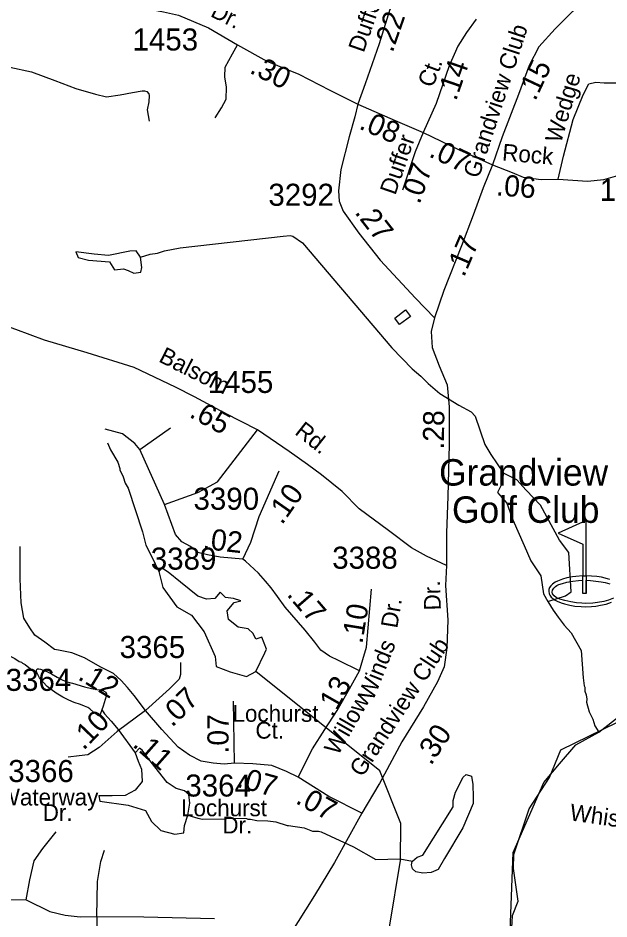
# Model space of a CAD drawing. Extents: x 1547597 to 1699558, y 810033 to 920809.
# Drawn here: x 1598301 to 1601652, y 878602 to 883710 of the extents above; entities that cross this region are included whole.
import ezdxf

# ---------------------------------------------------------------- set-up
doc = ezdxf.new("R2010")
doc.units = 0
for name, color, linetype in [('Exist Boundary Political City Limit New', 7, 'Continuous'), ('Exist Cultural Recreational Golf Course CELL', 7, 'Continuous'), ('Exist Cultural Recreational Golf Course Label', 7, 'Continuous'), ('Exist Hydrographic Creek Single Shore', 7, 'Continuous'), ('Exist Hydrographic Misc Water Feature', 7, 'Continuous'), ('Exist Road Non-System Type 51', 7, 'Continuous'), ('Exist Road Non-System Type 51 Label', 7, 'Continuous'), ('Exist Road Secondary Mileage Hundredths English Label', 7, 'Continuous'), ('Exist Road Secondary Type 51 Attributed', 7, 'Continuous'), ('Exist Road Secondary Type 51 Label', 7, 'Continuous'), ('Exist Road Secondary Type 51 Number Label', 7, 'Continuous'), ('Map Preparation Boundary City Limit Buffer Line', 7, 'Continuous')]:
    doc.layers.add(name, color=color, linetype=linetype)

msp = doc.modelspace()

# ---------------------------------------------------------------- linework, layer by layer
at = {"layer": 'Exist Boundary Political City Limit New'}
msp.add_lwpolyline([(1601102, 878552.4), (1601105.9, 878622.2), (1601138.3, 878702.8), (1601111, 878888.1), (1601113.6, 878968.7), (1601199.6, 879226.3), (1601315.8, 879403.5), (1601379.7, 879560.4), (1601858.9, 879795.7)], dxfattribs=at)
at = {"layer": 'Exist Cultural Recreational Golf Course CELL'}
for points in [[(1601657.7, 880526.5), (1601643.4, 880530.5), (1601610.4, 880539.3), (1601582.8, 880544.3), (1601523.3, 880548.2), (1601523.3, 880862.1), (1601364.8, 880788.7), (1601504.9, 880727.1), (1601504.9, 880548.2), (1601523.3, 880548.2), (1601523.3, 880523.2), (1601523.3, 880448.2), (1601523.3, 880523.2), (1601546.9, 880521.6), (1601577.5, 880518.4), (1601609, 880514.3), (1601630.2, 880510), (1601658, 880501.7)], [(1601677.2, 880420.8), (1601649.8, 880410.5), (1601623.3, 880403), (1601587.7, 880397.4), (1601560.7, 880393.4), (1601520.6, 880391.6), (1601498.1, 880393.4), (1601469.1, 880394.9), (1601436, 880399.4), (1601402, 880407), (1601372.9, 880415.5), (1601353.4, 880424), (1601341.4, 880433.5), (1601332.9, 880445.5), (1601330.4, 880455.5), (1601332.9, 880466.5), (1601339.9, 880477.5), (1601348.4, 880487.1), (1601357.5, 880492.4), (1601368.9, 880498.1), (1601388.1, 880504.6), (1601414.2, 880511.6), (1601447, 880517.6), (1601479.1, 880521.6), (1601504.9, 880523.2), (1601504.9, 880548.2), (1601523.3, 880548.2), (1601523.3, 880448.2), (1601504.9, 880448.2), (1601504.9, 880523.2), (1601504.9, 880548.2), (1601464.4, 880544.5), (1601444.9, 880542.8), (1601414.1, 880535.5), (1601388.6, 880529.2), (1601360.3, 880518.2), (1601347.9, 880511.1), (1601332.1, 880501.3), (1601321.9, 880490.3), (1601315.6, 880482.1), (1601311.6, 880469.8), (1601310.6, 880460), (1601313.4, 880445.5), (1601316.1, 880438.5), (1601325.1, 880426.2), (1601333.4, 880419.2), (1601347.3, 880409.6), (1601359, 880403.8), (1601381.6, 880394.3), (1601400.3, 880389.3), (1601430.6, 880382), (1601458.7, 880376.5), (1601495.1, 880373.2), (1601518.6, 880372.2), (1601552.4, 880374.2), (1601577.7, 880376.7), (1601604.1, 880381.3), (1601636.2, 880387.8), (1601667.2, 880398.3)]]:
    msp.add_lwpolyline(points, dxfattribs=at)
at = {"layer": 'Exist Hydrographic Creek Single Shore'}
for points in [[(1601039.7, 877845.7), (1600706.7, 877891.9), (1600549.6, 877993.5), (1600475.6, 878070.5), (1600386.6, 878230), (1600408, 878555), (1600469.4, 878933.7), (1600471.3, 879142.9), (1600352.4, 879442.3), (1599649.1, 880006)], [(1601076.6, 878137.2), (1601109.1, 878979.4), (1601282.9, 879376.8), (1601372, 879482), (1601463.8, 879588.8), (1601595.5, 879662.2), (1601723.6, 879762.2)]]:
    msp.add_lwpolyline(points, dxfattribs=at)
at = {"layer": 'Exist Hydrographic Misc Water Feature'}
msp.add_line((1600492.3, 878973), (1600492.3, 878973), dxfattribs=at)
for points in [[(1598995.8, 882353.6), (1599049.9, 882370.7), (1599091.5, 882377), (1599131.7, 882390.4), (1599219.9, 882406.9), (1599804.7, 882473.1), (1599844.8, 882476.4), (1599858.7, 882474.1), (1599914.1, 882435.2), (1600420.2, 881840.7), (1600536.3, 881720.8), (1600585.6, 881680), (1600626.9, 881637.3), (1600694, 881582.2), (1600800.8, 881514.4), (1600870.2, 881477.2), (1600893.8, 881452.8), (1600947.4, 881291.5), (1600982.4, 881234.9), (1601053.7, 881129.2)], [(1598995.8, 882353.6), (1598971.4, 882391.1), (1598934.8, 882388.5), (1598814.6, 882363.2), (1598733.6, 882371.1), (1598628.2, 882385), (1598641.3, 882351.9), (1598701.4, 882337.1), (1598819.9, 882327.5), (1598847.7, 882282.1), (1598900, 882289.1), (1598926.1, 882277.8), (1598957.5, 882263.8), (1598997.6, 882269.1), (1599002.8, 882296.1), (1598995.8, 882353.6)], [(1600497.8, 882055.6), (1600526.1, 882018.8), (1600465.2, 881972.4), (1600437.9, 882007.9), (1600497.8, 882055.6)], [(1598808.4, 881302), (1598825.7, 881261.7), (1598866.7, 881193), (1598878, 881156.8), (1598877.9, 881148.8), (1598897.3, 881108.5), (1598908.7, 881072.3), (1598926.2, 881044), (1599006.2, 880797), (1599025.2, 880720.8), (1599057.5, 880659.9), (1599099, 880571.4)], [(1601053.7, 881129.2), (1601039, 881057.7), (1601019.3, 881020.7), (1601073.4, 880959.1), (1601107.9, 880865.4), (1601172, 880720), (1601208.9, 880633.7), (1601265.5, 880547.5), (1601280.3, 880446.4), (1601304.9, 880402.5)], [(1601304.9, 880402.5), (1601405.9, 880434.1), (1601437.9, 880456.3), (1601425.6, 880680.6), (1601371.4, 880749.6), (1601263.1, 880949.2), (1601181.8, 881033), (1601130.1, 881092.2), (1601053.7, 881129.2)], [(1599649.1, 880006), (1599700, 880110.7), (1599709.5, 880131.6), (1599682.9, 880200.2), (1599648.7, 880188.7), (1599635.4, 880221.1), (1599606.8, 880247.7), (1599549.8, 880257.3), (1599494.6, 880301.1), (1599487, 880348.6), (1599526.9, 880396.2), (1599565, 880405.8), (1599523.1, 880419.1), (1599477.5, 880424.8), (1599447, 880455.3), (1599416.6, 880419.1), (1599369.1, 880415.3), (1599321.5, 880432.4), (1599222.6, 880512.4), (1599152.2, 880567.6), (1599114.2, 880592.3), (1599099, 880571.4)], [(1599099, 880571.4), (1599121.8, 880481.9), (1599201.7, 880371.5), (1599285.4, 880323.9), (1599355.7, 880230.6), (1599418.5, 880089.7), (1599424.2, 880034.5), (1599504.1, 880004.1), (1599597.3, 879977.4), (1599649.1, 880006)], [(1601304.9, 880402.5), (1601335.9, 880353.4), (1601363.3, 880312.9), (1601398.6, 880268.7), (1601437.9, 880225.1), (1601494.3, 880124.9), (1601505.8, 879968.6), (1601511.1, 879924.5), (1601514.9, 879916.5), (1601514.6, 879894.5), (1601522.2, 879872.3), (1601525.9, 879848.3), (1601525.6, 879832.4), (1601540.6, 879776.1), (1601560, 879735.8), (1601571.4, 879697.5), (1601595.5, 879662.2)], [(1598116.7, 880169.7), (1598144.2, 880141.3), (1598167.9, 880128.9), (1598175.9, 880128.7), (1598199.7, 880116.2), (1598231.6, 880105.8), (1598283.1, 880078.9), (1598306.9, 880062.5), (1598320.8, 880058.2), (1598326.7, 880052.2), (1598340.6, 880045.9), (1598382, 880013.2), (1598408, 880000.4)], [(1598408, 880000.4), (1598406, 880008.6), (1598407.2, 880016.3), (1598411.1, 880020.1), (1598419.4, 880021.1), (1598428.2, 880019.4), (1598463.9, 880004.5), (1598491.3, 879991.5), (1598522.1, 879972.9), (1598544, 879961.5), (1598573, 879949.6), (1598609.9, 879939.2), (1598678.1, 879918.5), (1598717.7, 879908.6), (1598748, 879903.8), (1598770.1, 879901.4), (1598786, 879895.6), (1598798.1, 879888.2), (1598802.9, 879879.4), (1598801.7, 879865.6), (1598784.4, 879809), (1598776.8, 879788.2)], [(1598776.8, 879788.2), (1598767.3, 879762.2), (1598763.9, 879755.7), (1598756.7, 879754.6), (1598750.2, 879759.1), (1598731, 879773.2), (1598708, 879793.3), (1598697.1, 879800.7), (1598678.4, 879809.7), (1598654.8, 879818.3), (1598620.2, 879829.8), (1598588.9, 879842.3), (1598554.9, 879859.8), (1598517, 879883), (1598488.6, 879902.6), (1598466.8, 879920.5), (1598442.8, 879944.6), (1598423.7, 879968.6), (1598409.2, 879995.3), (1598408, 880000.4)], [(1598776.8, 879788.2), (1598792.3, 879766.2), (1598829.6, 879724.5), (1598868.4, 879677.1), (1598966, 879543.4)], [(1599263.5, 879190.4), (1599276, 879259.3), (1599270.3, 879308.2), (1599244.4, 879328.3), (1599198.5, 879342.7), (1599146.8, 879375.7), (1599056.4, 879490.7), (1599004.7, 879559.7), (1598990.4, 879570.6), (1598966, 879543.4)], [(1598966, 879543.4), (1598983.2, 879497.9), (1599001.8, 879451.9), (1599004.7, 879381.5), (1598965.9, 879332.6), (1598908.5, 879302.4), (1598835.3, 879301), (1598759.2, 879301), (1598764.9, 879270.8), (1598925.7, 879247.8), (1599023.4, 879217.7), (1599057.8, 879154.4), (1599110.9, 879104.2), (1599189.9, 879082.6), (1599241.6, 879091.2), (1599244.4, 879132.9), (1599263.5, 879190.4)], [(1600538.7, 878929.7), (1600564.4, 878952.7), (1600596.1, 878964.6), (1600768.5, 879238.2), (1600768.5, 879273.9), (1600782.3, 879321.5), (1600825.9, 879406.8), (1600841.8, 879420.7), (1600873.5, 879412.7), (1600879.4, 879365.1), (1600881.4, 879293.8), (1600881.4, 879256.1), (1600823.9, 879119.3), (1600718.9, 878944.8), (1600683.3, 878883.3), (1600643.7, 878865.5), (1600596.1, 878861.5), (1600556.5, 878869.4), (1600538.7, 878887.3), (1600532.7, 878909.1), (1600536.7, 878928.9)], [(1599263.5, 879190.4), (1599320.1, 879173.5), (1599348, 879169), (1599476, 879170.9), (1599492.1, 879174.6), (1599596, 879172.9), (1599603.9, 879168.7), (1599619.9, 879168.5), (1599655.8, 879159.9), (1599717.7, 879158.9), (1599763.6, 879154), (1599827.2, 879132.9), (1599835.2, 879132.8), (1599924.6, 879120), (1599970.2, 879100.4), (1600004.6, 879099.8), (1600019.2, 879095.6), (1600203.9, 879011), (1600330.7, 878939.6), (1600465.4, 878943.6), (1600538.7, 878929.7)]]:
    msp.add_lwpolyline(points, dxfattribs=at)
at = {"layer": 'Exist Road Non-System Type 51'}
for p, q in [((1598991.3, 881263.8), (1599166.3, 881385.9)), ((1599131.3, 880951.7), (1598991.3, 881263.8))]:
    msp.add_line(p, q, dxfattribs=at)
for points in [[(1599418.1, 883143.9), (1599454.5, 883201.6), (1599480.9, 883249.2), (1599483.5, 883317.2), (1599474.1, 883377.3), (1599476.4, 883431.2), (1599517.2, 883506.9), (1599545.5, 883557.7)], [(1598144.3, 883451.3), (1598255.1, 883431.4), (1598376.8, 883404.4), (1598510.5, 883355.4), (1598628.1, 883310.4), (1598739.7, 883277.5), (1598803.4, 883263), (1598879.5, 883274.3), (1598949.6, 883287.7), (1599005.6, 883297.1), (1599018.8, 883297.5), (1599031.5, 883293), (1599042.9, 883280.8), (1599045.5, 883270.9), (1599043.2, 883234.9), (1599032.8, 883189.1), (1599044.1, 883125)], [(1598991.3, 881263.8), (1598963.4, 881297.7), (1598893.4, 881352), (1598795.4, 881379.1)], [(1599131.3, 880951.7), (1599320.2, 881019.5), (1599432.2, 881080.6), (1599659.5, 881375.6)], [(1599446.8, 880653), (1599376.2, 880666.7), (1599320.2, 880680.3), (1599278.2, 880714.2), (1599229.2, 880741.3), (1599194.3, 880782), (1599131.3, 880951.7)], [(1598529.6, 880126.3), (1598508.6, 880130.7), (1598452.6, 880171.4), (1598396.6, 880212.1), (1598368.6, 880252.8), (1598333.6, 880307.1), (1598319.6, 880395.3), (1598312.6, 880531), (1598312.6, 880714.2)], [(1598346.4, 878711.7), (1598367.7, 878824.6), (1598392.1, 878931.3), (1598440.9, 879001.5), (1598517.1, 879096)], [(1598748.7, 878617.1), (1598751.7, 878815.4), (1598770, 878928.3), (1598791.4, 878992.3)], [(1597934.9, 878717.8), (1598169.6, 878714.7), (1598346.4, 878711.7)], [(1598346.4, 878711.7), (1598480.5, 878644.6), (1598568.9, 878623.2), (1598654.2, 878614.1), (1598748.7, 878617.1)], [(1598748.7, 878617.1), (1598745.6, 878492.1), (1598736.5, 878284.7)], [(1598748.7, 878617.1), (1599013.8, 878614.1), (1599416.1, 878604.9)]]:
    msp.add_lwpolyline(points, dxfattribs=at)
at = {"layer": 'Exist Road Secondary Type 51 Attributed'}
for p, q in [((1599575.7, 880642), (1599446.8, 880653)), ((1599529.4, 879485.2), (1599523.3, 879838.1))]:
    msp.add_line(p, q, dxfattribs=at)
for points in [[(1600802.3, 884212.6), (1600720.2, 884144.8), (1600628.8, 884047.9), (1600566.2, 883978.6), (1600492.5, 883898.9), (1600409.4, 883757.8), (1600349, 883563.6), (1600270.2, 883337.6), (1600227.5, 883221.2)], [(1598855.7, 883794.1), (1598974.8, 883773.9), (1599125.6, 883745.4), (1599211.2, 883727), (1599380.4, 883653.6), (1599545.5, 883557.7), (1599712.3, 883465.8), (1599893.2, 883390.9), (1600068.5, 883300.8), (1600227.5, 883221.2)], [(1601495.6, 883794.9), (1601430.7, 883732.2), (1601347.7, 883649), (1601253.9, 883547), (1601199.1, 883440), (1601138.9, 883276.9), (1601046.9, 883036.9), (1600992.2, 882877.2)], [(1600899.6, 883704.4), (1600844, 883627.8), (1600795.3, 883551.2), (1600745.9, 883438.7), (1600672.1, 883225.5), (1600597.9, 883061.2)], [(1601363.8, 882796.1), (1601393.7, 882926.8), (1601448.6, 883134.1), (1601506.4, 883273.7), (1601537.6, 883337), (1601577, 883347.2), (1601625, 883342.9), (1601762.9, 883342.9), (1601999.8, 883331.2), (1602258.1, 883329.3), (1602434.9, 883325.4)], [(1600227.5, 883221.2), (1600210.5, 883150.1), (1600178.5, 883036.6), (1600131.6, 882850.8), (1600118.3, 882730.2), (1600122, 882672.1), (1600145.4, 882616), (1600234.4, 882491.3), (1600355.1, 882336.4), (1600555.3, 882122.8), (1600663.1, 882009.6)], [(1600227.5, 883221.2), (1600438.9, 883128.6), (1600597.9, 883061.2)], [(1600597.9, 883061.2), (1600553, 882951.1), (1600481.7, 882734.8)], [(1600597.9, 883061.2), (1600802.6, 882962.5), (1600992.2, 882877.2)], [(1601363.8, 882796.1), (1601531.1, 882784.5), (1601622.4, 882794.8), (1601755, 882832.7), (1601977.2, 882884.4), (1602245.8, 882937.9), (1602407.7, 882960.3)], [(1600992.2, 882877.2), (1600938.9, 882747.2), (1600882, 882591.9), (1600815.3, 882418.3), (1600716.5, 882164.5), (1600663.1, 882009.6)], [(1600992.2, 882877.2), (1601102.9, 882834.6), (1601166.5, 882807.9), (1601268, 882794.1), (1601363.8, 882796.1)], [(1600730.5, 880607), (1600618.4, 880660.1), (1600532.8, 880707), (1600402.4, 880804.9), (1600235.2, 880927.3), (1600139.4, 881025.2), (1600021.2, 881121.1), (1599941.7, 881178.2), (1599838.9, 881253.2), (1599659.5, 881375.6), (1599474.7, 881470.8), (1599301.4, 881562.6), (1599193.5, 881617.5), (1598959.3, 881729.3), (1598692.2, 881811.1), (1598451.7, 881884.6), (1598288.6, 881943.7), (1598196.9, 881976.3), (1598122.1, 882002.9), (1597963.1, 882048.7), (1597816.2, 882086.1)], [(1600663.1, 882009.6), (1600644.5, 881932.1), (1600650.3, 881841.3), (1600689.5, 881739.1), (1600735.4, 881630.4), (1600746.1, 881506), (1600746.1, 881292.7), (1600739, 880997.6), (1600731.4, 880792.4), (1600730.5, 880607)], [(1599575.7, 880642), (1599620.5, 880737.9), (1599669.4, 880884.8), (1599781.5, 881143.8)], [(1600236.8, 880008.5), (1600121.9, 880065.2), (1600067, 880092.9), (1600018, 880126.8), (1599983.3, 880171.2), (1599928.9, 880239.2), (1599815.2, 880370.9), (1599772.4, 880430), (1599736.7, 880478.8), (1599704.1, 880517.5), (1599665.4, 880562.4), (1599591, 880631.8), (1599575.7, 880642)], [(1600730.5, 880607), (1600724.4, 880492.8), (1600739.3, 880296.3), (1600732.1, 880138.6), (1600718.5, 880031.2), (1600679.8, 879947.5), (1600600.3, 879804.7), (1600478.3, 879606), (1600351, 879371.2), (1600347.5, 879365.3), (1600251.4, 879201.9)], [(1600236.8, 880008.5), (1600256.2, 880073.7), (1600276.6, 880143.1), (1600305.1, 880471.5)], [(1599023.9, 879785.1), (1598959.3, 879868.6), (1598922.6, 879915.5), (1598885.9, 879954.3), (1598843.1, 879993.1), (1598767.7, 880031.8), (1598678, 880082.8), (1598606.5, 880110.3), (1598529.6, 880126.3)], [(1599222.2, 880056), (1599222.2, 879988.2), (1599215.3, 879961.1), (1599159.3, 879906.8), (1599023.9, 879785.1)], [(1599889.5, 879406), (1599970.9, 879567.5), (1600040.9, 879676.1), (1600110.9, 879784.6), (1600180.8, 879906.8), (1600236.8, 880008.5)], [(1599023.9, 879785.1), (1598862.6, 879664.7), (1598760.4, 879574.3), (1598697.5, 879533.6), (1598648.5, 879526.8), (1598585.5, 879520)], [(1599529.4, 879485.2), (1599470.3, 879479.1), (1599407.1, 879485.2), (1599339.8, 879497.4), (1599272.6, 879530.1), (1599209.4, 879577), (1599115.6, 879676.9), (1599023.9, 879785.1)], [(1599889.5, 879406), (1599824.3, 879438.6), (1599740, 879472.5), (1599633.4, 879481.1), (1599529.4, 879485.2)], [(1600251.4, 879201.9), (1600064.1, 879297.4), (1599889.5, 879406)], [(1600251.4, 879201.9), (1600094.9, 878923.3), (1599981.5, 878735.9), (1599838.7, 878507.4), (1599735.8, 878339.5), (1599643.8, 878171.5), (1599557.2, 878041.5), (1599471.8, 877926.7), (1599437.6, 877882), (1599421.9, 877847.8), (1599410, 877804.4), (1599406.1, 877734.7), (1599406.1, 877612.3), (1599404.8, 877490)]]:
    msp.add_lwpolyline(points, dxfattribs=at)
at = {"layer": 'Map Preparation Boundary City Limit Buffer Line'}
msp.add_lwpolyline([(1601102, 878552.4), (1601105.9, 878622.2), (1601138.3, 878702.8), (1601111, 878888.1), (1601113.6, 878968.7), (1601199.6, 879226.3), (1601315.8, 879403.5), (1601379.7, 879560.4), (1601858.9, 879795.7)], dxfattribs=at)

# ---------------------------------------------------------------- texts
at = {"layer": 'Exist Cultural Recreational Golf Course Label'}
for s, p in [('Grandview', (1600688.8, 881059.2)), ('Golf Club', (1600762, 880848.1))]:
    msp.add_text(s, height=150, dxfattribs=at).set_placement(p)
at = {"layer": 'Exist Road Non-System Type 51 Label'}
msp.add_text('Whispering', height=95, rotation=351.9683, dxfattribs=at).set_placement((1601425.8, 879161.9))
at = {"layer": 'Exist Road Secondary Mileage Hundredths English Label'}
for s, rotation, p in [('.22', 70.7283, (1600424.7, 883509.8)), ('.30', 333.5077, (1599608.4, 883401.7)), ('.14', 70.9154, (1600785.1, 883236)), ('.15', 64.8314, (1601234.1, 883235.5)), ('.08', 336.3311, (1600229.4, 883084.7)), ('.07', 334.4013, (1600625.3, 882927.3)), ('.07', 70.6507, (1600577.9, 882650.4)), ('.06', 355.6555, (1601010, 882705.1)), ('.27', 307.9246, (1600206.6, 882606.9)), ('.17', 66.849, (1600830.2, 882236.6)), ('.65', 331.3198, (1599266.7, 881451.4)), ('.28', 89.321, (1600716.3, 881262.8)), ('.10', 55.0437, (1599798, 880832.7)), ('.02', 353.4921, (1599345.3, 880701.2)), ('.17', 310.826, (1599821.1, 880439.3)), ('.10', 80.7453, (1600253.7, 880158.7)), ('.12', 328.7817, (1598634.8, 879964)), ('.13', 60.1907, (1600085, 879740.1)), ('.07', 44.1186, (1599174.7, 879686)), ('.10', 45.967, (1598673.2, 879554.8)), ('.07', 90, (1599494.9, 879540.4)), ('.30', 56.6782, (1600642.9, 879468.3)), ('.11', 318.3661, (1598945.6, 879584.8)), ('.07', 344.5142, (1599535.8, 879353)), ('.07', 331.2116, (1599869.2, 879261.5))]:
    msp.add_text(s, height=120, rotation=rotation, dxfattribs=at).set_placement(p)
at = {"layer": 'Exist Road Secondary Type 51 Label'}
for s, rotation, p in [('Duffer', 70.7283, (1600261.1, 883509.6)), ('Dr.', 333.2262, (1599386.7, 883721.9)), ('Grandview Club', 71.9652, (1600913.8, 882796.7)), ('Ct.', 69.4606, (1600653.6, 883310.5)), ('Wedge', 73.5655, (1601379.6, 882996)), ('Duffer', 70.9154, (1600440.4, 882702)), ('Rock', 354.9237, (1601043.9, 882903.2)), ('Balsom', 333.2574, (1599093.3, 881764.4)), ('Rd.', 321.7388, (1599865.2, 881354.7)), ('Dr.', 91.7246, (1600699.3, 880353.1)), ('Dr.', 80.7453, (1600451.5, 880247)), ('Grandview Club', 56.6782, (1600253.7, 879401.6)), ('Winds', 68.1683, (1600313.8, 879834.3)), ('Willow', 60.1907, (1600115.2, 879524.5))]:
    msp.add_text(s, height=95, rotation=rotation, dxfattribs=at).set_placement(p)
for s, p in [('Lochurst', (1599517.3, 879720.1)), ('Ct.', (1599647.3, 879624.7)), ('Waterway', (1598191.8, 879245.7)), ('Lochurst', (1599225.5, 879184.7)), ('Dr.', (1598441.2, 879158.2)), ('Dr.', (1599459.9, 879087.1))]:
    msp.add_text(s, height=95, dxfattribs=at).set_placement(p)
at = {"layer": 'Exist Road Secondary Type 51 Number Label'}
for s, p in [('1453', (1598950.5, 883525.9)), ('1453', (1601599.9, 882673.4)), ('3292', (1599720.8, 882645.6)), ('1455', (1599377, 881584.6)), ('3390', (1599296.2, 880922.3)), ('3389', (1599054, 880582.8)), ('3388', (1600082.7, 880587.9)), ('3365', (1598877.1, 880081.7)), ('3364', (1598230.8, 879895.5)), ('3366', (1598245.4, 879378.7)), ('3364', (1599249.9, 879296.4))]:
    msp.add_text(s, height=125, dxfattribs=at).set_placement(p)

doc.saveas('drawing.dxf')
